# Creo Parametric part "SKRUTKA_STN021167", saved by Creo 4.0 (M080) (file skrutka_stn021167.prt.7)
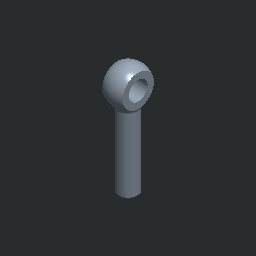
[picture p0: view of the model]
Units: millimeter Kilogram Sec (mmKs); MM, KILOGRAM, SECS
Materials in the file: OCEL_N

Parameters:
  MFG_WP_MATERIAL = "OCEL"
  NAZOV = "SKRUTKA_STN021167"
  NORMA = "STN 02 1167"
  PTC_MATERIAL_NAME = "OCEL_N"

Other parameters: HMOTNOST, HUSTOTA, D16, D11, D8

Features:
  1. round
  2. chamfer
  3. datum plane "DTM1"
  4. cut
  5. cut
  6. cut
  7. datum plane "DTM2"
  8. datum plane "DTM3"

Other named items: BLIND

Layers: 1, 2, 3, 4, 5, 6, 7, 8, 9, 10, 11, 12, 13, 14, 15, 16, 17, 18, 19, 20, 21, 22, 23, 24, 25, 26, 27, 28, 29, 30, 31, 32

Family table entries: GENERIC, SKRUTKA_M3, SKRUTKA_STN021167, value(d_val), 2/ , value(i_val), SKRUTKA_M4, SKRUTKA_STN021167, 2/$, SKRUTKA_M5, SKRUTKA_STN021167, 2/(, SKRUTKA_M6, SKRUTKA_STN021167, 2/,, SKRUTKA_M8, SKRUTKA_STN021167, !/ , 2/2, 2/", SKRUTKA_M10, SKRUTKA_STN021167, !/$, 2/4, 2/(, SKRUTKA_M12, SKRUTKA_STN021167, !/(, 2/9, 2/,, SKRUTKA_M14, SKRUTKA_STN021167, !/,, 2/<, 2/0, SKRUTKA_M16, SKRUTKA_STN021167, !/0, 2/@, 2/1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

Surfaces: 6 plane, 5 cylinder, 4 torus, 2 cone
